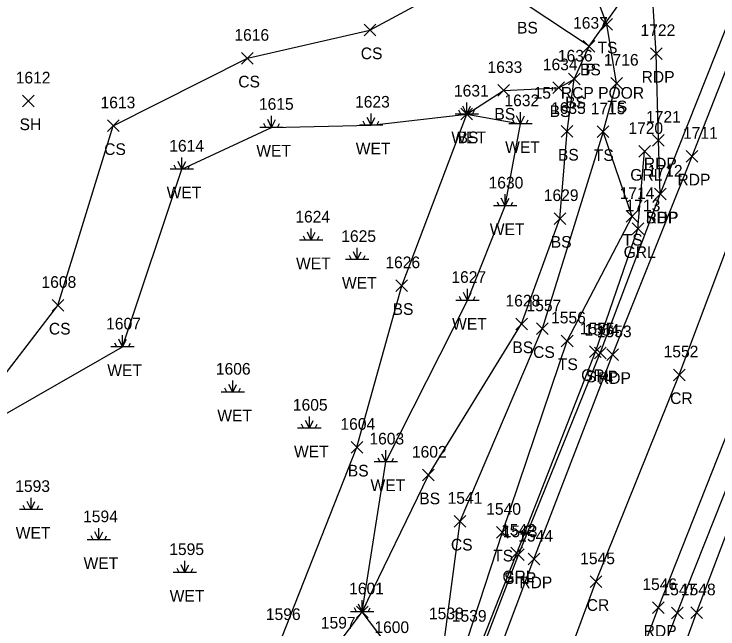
# Model space of a CAD drawing. Extents: x 1554917 to 1555870, y 813367 to 816333.
# Drawn here: x 1555138.3 to 1555258.8, y 814056.2 to 814161.6 of the extents above; entities that cross this region are included whole.
import ezdxf

# ---------------------------------------------------------------- set-up
doc = ezdxf.new("R2010")
doc.units = 0
for name, color, linetype in [('D_A', 7, 'Continuous'), ('D_C', 7, 'Continuous'), ('D_I', 7, 'Continuous'), ('D_TIC', 7, 'Continuous'), ('DCP', 7, 'Continuous'), ('L_A', 7, 'Continuous'), ('L_I', 7, 'Continuous'), ('L_TIC', 7, 'Continuous'), ('LELB', 7, 'Continuous'), ('LWET', 7, 'Continuous'), ('P_A', 7, 'Continuous'), ('P_I', 7, 'Continuous'), ('P_TIC', 7, 'Continuous'), ('PET', 7, 'Continuous'), ('PRC', 7, 'Continuous'), ('PSP', 7, 'Continuous'), ('R_A', 7, 'Continuous'), ('R_I', 7, 'Continuous'), ('R_TIC', 7, 'Continuous'), ('RGR', 7, 'Continuous')]:
    doc.layers.add(name, color=color, linetype=linetype)

msp = doc.modelspace()

# ---------------------------------------------------------------- linework, layer by layer
at = {"layer": 'D_TIC'}
for points in [[(1555235.77, 814155.09), (1555237.77, 814157.09)], [(1555237.77, 814155.09), (1555235.77, 814157.09)]]:
    msp.add_lwpolyline(points, dxfattribs=at)
at = {"layer": 'DCP'}
msp.add_lwpolyline([(1555236.77, 814156.09), (1555266.03, 814197.26)], dxfattribs=at)
at = {"layer": 'L_TIC'}
for points in [[(1555238.8, 814158.84), (1555240.8, 814160.84)], [(1555240.8, 814158.84), (1555238.8, 814160.84)], [(1555198.22, 814157.86), (1555200.22, 814159.86)], [(1555200.22, 814157.86), (1555198.22, 814159.86)], [(1555235.77, 814155.09), (1555237.77, 814157.09)], [(1555237.77, 814155.09), (1555235.77, 814157.09)], [(1555177.24, 814153.02), (1555179.24, 814155.02)], [(1555179.24, 814153.02), (1555177.24, 814155.02)], [(1555233.22, 814149.46), (1555235.22, 814151.46)], [(1555235.22, 814149.46), (1555233.22, 814151.46)], [(1555233.22, 814149.46), (1555235.22, 814151.46)], [(1555235.22, 814149.46), (1555233.22, 814151.46)], [(1555240.48, 814148.75), (1555242.48, 814150.75)], [(1555242.48, 814148.75), (1555240.48, 814150.75)], [(1555230.58, 814147.96), (1555232.58, 814149.96)], [(1555232.58, 814147.96), (1555230.58, 814149.96)], [(1555221.11, 814147.5), (1555223.11, 814149.5)], [(1555223.11, 814147.5), (1555221.11, 814149.5)], [(1555139.73, 814145.7), (1555141.73, 814147.7)], [(1555141.73, 814145.7), (1555139.73, 814147.7)], [(1555214.8, 814143.46), (1555216.8, 814145.46)], [(1555216.8, 814143.46), (1555214.8, 814145.46)], [(1555154.27, 814141.44), (1555156.27, 814143.44)], [(1555156.27, 814141.44), (1555154.27, 814143.44)], [(1555231.99, 814140.48), (1555233.99, 814142.48)], [(1555233.99, 814140.48), (1555231.99, 814142.48)], [(1555238.17, 814140.42), (1555240.17, 814142.42)], [(1555240.17, 814140.42), (1555238.17, 814142.42)], [(1555243.12, 814125.91), (1555245.12, 814127.91)], [(1555245.12, 814125.91), (1555243.12, 814127.91)], [(1555230.76, 814125.55), (1555232.76, 814127.55)], [(1555232.76, 814125.55), (1555230.76, 814127.55)], [(1555203.67, 814114.04), (1555205.67, 814116.04)], [(1555205.67, 814114.04), (1555203.67, 814116.04)], [(1555144.8, 814110.67), (1555146.8, 814112.67)], [(1555146.8, 814110.67), (1555144.8, 814112.67)], [(1555224.19, 814107.48), (1555226.19, 814109.48)], [(1555226.19, 814107.48), (1555224.19, 814109.48)], [(1555227.74, 814106.66), (1555229.74, 814108.66)], [(1555229.74, 814106.66), (1555227.74, 814108.66)], [(1555232.01, 814104.58), (1555234.01, 814106.58)], [(1555234.01, 814104.58), (1555232.01, 814106.58)], [(1555196, 814086.34), (1555198, 814088.34)], [(1555198, 814086.34), (1555196, 814088.34)], [(1555208.24, 814081.57), (1555210.24, 814083.57)], [(1555210.24, 814081.57), (1555208.24, 814083.57)], [(1555213.66, 814073.66), (1555215.66, 814075.66)], [(1555215.66, 814073.66), (1555213.66, 814075.66)], [(1555220.93, 814071.78), (1555222.93, 814073.78)], [(1555222.93, 814071.78), (1555220.93, 814073.78)], [(1555196.92, 814058.14), (1555198.92, 814060.14)], [(1555198.92, 814058.14), (1555196.92, 814060.14)], [(1555254.18, 814057.98), (1555256.18, 814059.98)], [(1555256.18, 814057.98), (1555254.18, 814059.98)]]:
    msp.add_lwpolyline(points, dxfattribs=at)
at = {"layer": 'LELB'}
for points in [[(1555161.57, 813925.65), (1555168.92, 813938.89), (1555173.57, 813945.95), (1555174.16, 813952.01), (1555182.4, 813974.26), (1555190.04, 813992.11), (1555201.74, 814019.14), (1555212.19, 814045.46), (1555215.96, 814054.45), (1555221.93, 814072.78), (1555233.01, 814105.58), (1555244.12, 814126.91), (1555239.17, 814141.42), (1555241.48, 814149.75), (1555239.8, 814159.84), (1555236.73, 814168.01), (1555231.65, 814185.57), (1555238.6, 814201.71), (1555239.91, 814224.12), (1555242.5, 814231.73), (1555248.59, 814255.34), (1555259.33, 814293.88), (1555265.42, 814329.58), (1555267.14, 814335.72)], [(1555103.83, 814081.29), (1555127.34, 814087.63), (1555145.8, 814111.67), (1555155.27, 814142.44), (1555178.24, 814154.02), (1555199.22, 814158.86), (1555221.17, 814170.73)], [(1555153.95, 813930.09), (1555158.29, 813940), (1555164.03, 813953.38), (1555164.41, 813963.6), (1555171.65, 813982.26), (1555182.05, 814007.23), (1555196.6, 814047.94), (1555202.45, 814046.5), (1555202.9, 814052.51), (1555197.92, 814059.14), (1555209.24, 814082.57), (1555225.19, 814108.48), (1555231.76, 814126.55), (1555232.99, 814141.48), (1555234.22, 814150.46), (1555236.77, 814156.09), (1555225.98, 814163.26)], [(1555146.26, 813968.15), (1555143.26, 813995.13), (1555159.28, 814011.16), (1555184.15, 814054.74), (1555197, 814087.34), (1555204.67, 814115.04), (1555215.8, 814144.46), (1555222.11, 814148.5), (1555231.58, 814148.96), (1555234.22, 814150.46)], [(1555239.17, 814141.42), (1555228.74, 814107.66)], [(1555244.11, 813903.09), (1555240.76, 813916.62), (1555228.48, 813937.37), (1555217.61, 813950.51), (1555215.58, 813954.88), (1555216.99, 813960.62), (1555222.34, 813976.41), (1555235.01, 814010.77), (1555239.56, 814017.88), (1555245.78, 814033.09), (1555255.18, 814058.98), (1555268.47, 814094.07), (1555274.97, 814112.22), (1555278.17, 814116.24), (1555282.02, 814117.52), (1555286.39, 814116.11), (1555289.99, 814109.88), (1555296.54, 814106.47), (1555313.61, 814126.36), (1555333.57, 814137.64)], [(1555212.19, 814045.46), (1555212.03, 814054.87), (1555214.66, 814074.66), (1555228.74, 814107.66)]]:
    msp.add_lwpolyline(points, dxfattribs=at)
at = {"layer": 'LWET'}
for p, q in [((1555215.8, 814144.46), (1555215.8, 814146.46)), ((1555214.8, 814144.46), (1555214.46, 814145.12)), ((1555215.8, 814144.46), (1555215.13, 814145.79)), ((1555215.8, 814144.46), (1555216.46, 814145.79)), ((1555216.8, 814144.46), (1555217.13, 814145.12)), ((1555225.01, 814142.8), (1555225.01, 814144.8)), ((1555225.01, 814142.8), (1555225.01, 814144.8)), ((1555182.39, 814142.18), (1555181.73, 814143.51)), ((1555182.39, 814142.18), (1555182.39, 814144.18)), ((1555182.39, 814142.18), (1555183.06, 814143.51)), ((1555199.42, 814142.56), (1555198.76, 814143.89)), ((1555199.42, 814142.56), (1555199.42, 814144.56)), ((1555199.42, 814142.56), (1555200.09, 814143.89)), ((1555217.8, 814144.46), (1555213.8, 814144.46)), ((1555225.01, 814142.8), (1555224.34, 814144.13)), ((1555225.01, 814142.8), (1555224.34, 814144.13)), ((1555225.01, 814142.8), (1555225.68, 814144.13)), ((1555225.01, 814142.8), (1555225.68, 814144.13)), ((1555181.39, 814142.18), (1555181.06, 814142.85)), ((1555183.39, 814142.18), (1555183.73, 814142.85)), ((1555201.42, 814142.56), (1555197.42, 814142.56)), ((1555198.42, 814142.56), (1555198.09, 814143.23)), ((1555200.42, 814142.56), (1555200.76, 814143.23)), ((1555227.01, 814142.8), (1555223.01, 814142.8)), ((1555227.01, 814142.8), (1555223.01, 814142.8)), ((1555224.01, 814142.8), (1555223.68, 814143.46)), ((1555224.01, 814142.8), (1555223.68, 814143.46)), ((1555226.01, 814142.8), (1555226.34, 814143.46)), ((1555226.01, 814142.8), (1555226.34, 814143.46)), ((1555184.39, 814142.18), (1555180.39, 814142.18)), ((1555167.03, 814135.02), (1555166.36, 814136.35)), ((1555167.03, 814135.02), (1555167.03, 814137.02)), ((1555167.03, 814135.02), (1555167.7, 814136.35)), ((1555166.03, 814135.02), (1555165.7, 814135.69)), ((1555168.03, 814135.02), (1555168.36, 814135.69)), ((1555169.03, 814135.02), (1555165.03, 814135.02)), ((1555222.38, 814128.7), (1555222.38, 814130.7)), ((1555221.38, 814128.7), (1555221.05, 814129.36)), ((1555222.38, 814128.7), (1555221.71, 814130.03)), ((1555222.38, 814128.7), (1555223.05, 814130.03)), ((1555223.38, 814128.7), (1555223.71, 814129.36)), ((1555224.38, 814128.7), (1555220.38, 814128.7)), ((1555189.19, 814122.87), (1555189.19, 814124.87)), ((1555188.19, 814122.87), (1555187.86, 814123.53)), ((1555189.19, 814122.87), (1555188.52, 814124.2)), ((1555189.19, 814122.87), (1555189.86, 814124.2)), ((1555190.19, 814122.87), (1555190.52, 814123.53)), ((1555191.19, 814122.87), (1555187.19, 814122.87)), ((1555197.06, 814119.54), (1555196.4, 814120.87)), ((1555197.06, 814119.54), (1555197.06, 814121.54)), ((1555197.06, 814119.54), (1555197.73, 814120.87)), ((1555199.06, 814119.54), (1555195.06, 814119.54)), ((1555196.06, 814119.54), (1555195.73, 814120.21)), ((1555198.06, 814119.54), (1555198.4, 814120.21)), ((1555215.92, 814112.52), (1555215.25, 814113.85)), ((1555215.92, 814112.52), (1555215.92, 814114.52)), ((1555215.92, 814112.52), (1555216.59, 814113.85)), ((1555217.92, 814112.52), (1555213.92, 814112.52)), ((1555214.92, 814112.52), (1555214.59, 814113.19)), ((1555216.92, 814112.52), (1555217.25, 814113.19)), ((1555156.87, 814104.54), (1555156.87, 814106.54)), ((1555155.87, 814104.54), (1555155.54, 814105.21)), ((1555156.87, 814104.54), (1555156.21, 814105.87)), ((1555156.87, 814104.54), (1555157.54, 814105.87)), ((1555157.87, 814104.54), (1555158.21, 814105.21)), ((1555158.87, 814104.54), (1555154.87, 814104.54)), ((1555175.72, 814096.79), (1555175.05, 814098.12)), ((1555175.72, 814096.79), (1555175.72, 814098.79)), ((1555175.72, 814096.79), (1555176.38, 814098.12)), ((1555177.72, 814096.79), (1555173.72, 814096.79)), ((1555174.72, 814096.79), (1555174.38, 814097.46)), ((1555176.72, 814096.79), (1555177.05, 814097.46)), ((1555188.85, 814090.62), (1555188.18, 814091.96)), ((1555188.85, 814090.62), (1555188.85, 814092.62)), ((1555188.85, 814090.62), (1555189.51, 814091.96)), ((1555190.85, 814090.62), (1555186.85, 814090.62)), ((1555187.85, 814090.62), (1555187.51, 814091.29)), ((1555189.85, 814090.62), (1555190.18, 814091.29)), ((1555201.96, 814084.83), (1555201.29, 814086.17)), ((1555201.96, 814084.83), (1555201.96, 814086.83)), ((1555201.96, 814084.83), (1555202.62, 814086.17)), ((1555203.96, 814084.83), (1555199.96, 814084.83)), ((1555200.96, 814084.83), (1555200.62, 814085.5)), ((1555202.96, 814084.83), (1555203.29, 814085.5)), ((1555141.18, 814076.69), (1555141.18, 814078.69)), ((1555140.18, 814076.69), (1555139.84, 814077.36)), ((1555141.18, 814076.69), (1555140.51, 814078.03)), ((1555141.18, 814076.69), (1555141.84, 814078.03)), ((1555142.18, 814076.69), (1555142.51, 814077.36)), ((1555143.18, 814076.69), (1555139.18, 814076.69)), ((1555152.8, 814071.5), (1555152.13, 814072.84)), ((1555152.8, 814071.5), (1555152.8, 814073.5)), ((1555152.8, 814071.5), (1555153.46, 814072.84)), ((1555154.8, 814071.5), (1555150.8, 814071.5)), ((1555151.8, 814071.5), (1555151.46, 814072.17)), ((1555153.8, 814071.5), (1555154.13, 814072.17)), ((1555167.55, 814065.88), (1555167.55, 814067.88)), ((1555166.55, 814065.88), (1555166.22, 814066.55)), ((1555167.55, 814065.88), (1555166.89, 814067.22)), ((1555167.55, 814065.88), (1555168.22, 814067.22)), ((1555168.55, 814065.88), (1555168.89, 814066.55)), ((1555169.55, 814065.88), (1555165.55, 814065.88)), ((1555197.92, 814059.14), (1555197.25, 814060.47)), ((1555197.92, 814059.14), (1555197.92, 814061.14)), ((1555197.92, 814059.14), (1555198.59, 814060.47)), ((1555199.92, 814059.14), (1555195.92, 814059.14)), ((1555196.92, 814059.14), (1555196.59, 814059.81)), ((1555198.92, 814059.14), (1555199.25, 814059.81))]:
    msp.add_line(p, q, dxfattribs=at)
for points in [[(1555103.17, 814066.14), (1555127.34, 814087.63), (1555156.87, 814104.54), (1555167.03, 814135.02), (1555182.39, 814142.18), (1555199.42, 814142.56), (1555215.8, 814144.46), (1555225.01, 814142.8)], [(1555079.52, 813972.15), (1555098.48, 813965.44), (1555111.92, 813965.76), (1555124.09, 813958.62), (1555134.73, 813947.78), (1555144.25, 813942.2), (1555154.27, 813942.5), (1555154.52, 813966.83), (1555160.01, 813989.73), (1555171.92, 814009.61), (1555193.51, 814053.28), (1555197.92, 814059.14), (1555201.96, 814084.83), (1555215.92, 814112.52), (1555222.38, 814128.7), (1555225.01, 814142.8)]]:
    msp.add_lwpolyline(points, dxfattribs=at)
at = {"layer": 'P_TIC'}
for points in [[(1555247.27, 814153.83), (1555249.27, 814155.83)], [(1555249.27, 814153.83), (1555247.27, 814155.83)], [(1555247.65, 814138.98), (1555249.65, 814140.98)], [(1555249.65, 814138.98), (1555247.65, 814140.98)], [(1555253.41, 814136.22), (1555255.41, 814138.22)], [(1555255.41, 814136.22), (1555253.41, 814138.22)], [(1555247.96, 814129.73), (1555249.96, 814131.73)], [(1555249.96, 814129.73), (1555247.96, 814131.73)], [(1555247.96, 814129.73), (1555249.96, 814131.73)], [(1555249.96, 814129.73), (1555247.96, 814131.73)], [(1555237.68, 814102.48), (1555239.68, 814104.48)], [(1555239.68, 814102.48), (1555237.68, 814104.48)], [(1555239.79, 814102.21), (1555241.79, 814104.21)], [(1555241.79, 814102.21), (1555239.79, 814104.21)], [(1555251.22, 814098.76), (1555253.22, 814100.76)], [(1555253.22, 814098.76), (1555251.22, 814100.76)], [(1555223.66, 814067.93), (1555225.66, 814069.93)], [(1555225.66, 814067.93), (1555223.66, 814069.93)], [(1555226.32, 814067.19), (1555228.32, 814069.19)], [(1555228.32, 814067.19), (1555226.32, 814069.19)], [(1555236.93, 814063.31), (1555238.93, 814065.31)], [(1555238.93, 814063.31), (1555236.93, 814065.31)], [(1555247.64, 814058.88), (1555249.64, 814060.88)], [(1555249.64, 814058.88), (1555247.64, 814060.88)], [(1555250.86, 814057.97), (1555252.86, 814059.97)], [(1555252.86, 814057.97), (1555250.86, 814059.97)]]:
    msp.add_lwpolyline(points, dxfattribs=at)
at = {"layer": 'PET'}
for points in [[(1555161.36, 813900.53), (1555183.5, 813956.99), (1555189.63, 813971.7), (1555196.36, 813987.75), (1555203.89, 814008), (1555206.01, 814012.95), (1555218.07, 814043.52), (1555227.32, 814068.19), (1555240.79, 814103.21), (1555254.41, 814137.22), (1555273.72, 814186.43), (1555286.72, 814219.57), (1555303.34, 814262.32), (1555319.11, 814302.56), (1555330.34, 814331.97)], [(1555182.57, 813892.25), (1555203.7, 813945.01), (1555216.85, 813978.34), (1555228.72, 814008.85), (1555239.47, 814035.47), (1555248.64, 814059.88), (1555262.92, 814096.01), (1555276.68, 814131.3), (1555286.36, 814156.33), (1555297.11, 814184.04), (1555306.67, 814209.51), (1555324.28, 814253.26), (1555340.35, 814293.54), (1555352.6, 814325.05)], [(1555248.96, 814130.73), (1555248.65, 814139.98), (1555248.27, 814154.83), (1555247.26, 814170.29), (1555253.74, 814178.64), (1555260.71, 814192.35), (1555263.33, 814182.56), (1555266.01, 814181.4), (1555270.99, 814187.05)]]:
    msp.add_lwpolyline(points, dxfattribs=at)
at = {"layer": 'PRC'}
msp.add_lwpolyline([(1554976.76, 813382.18), (1554992.84, 813427.9), (1555014.07, 813486.01), (1555030.62, 813532.31), (1555046.37, 813573.08), (1555064.69, 813621.19), (1555082.41, 813667.53), (1555112.1, 813744.1), (1555110.69, 813739.79), (1555136.16, 813805.74), (1555152.52, 813846.93), (1555172.03, 813896.18), (1555193.96, 813951.2), (1555206.37, 813983.4), (1555218.13, 814013.22), (1555228.65, 814039.26), (1555237.93, 814064.31), (1555252.22, 814099.76), (1555265.8, 814135.89), (1555275.26, 814160.09), (1555297.17, 814214.77), (1555313.83, 814257.94), (1555329.72, 814298.26), (1555342.03, 814329.92)], dxfattribs=at)
at = {"layer": 'PSP'}
for points in [[(1555160.79, 813906.47), (1555173.05, 813937.33), (1555179.42, 813953.63), (1555181.24, 813957.84), (1555186.72, 813973.16), (1555194.02, 813990.9), (1555204.38, 814016.29), (1555205.03, 814017.75), (1555215.29, 814044.5), (1555224.66, 814068.93), (1555238.68, 814103.48), (1555248.96, 814130.73), (1555261.62, 814162.67), (1555270.99, 814187.05), (1555283.98, 814220.8), (1555300.65, 814263.34), (1555316.51, 814303.51), (1555327.36, 814331.38)], [(1555197.67, 813922.42), (1555211.91, 813956.86), (1555220.23, 813977.15), (1555231.8, 814008.2), (1555242.48, 814034.48), (1555251.86, 814058.97), (1555266.04, 814094.8), (1555272.79, 814112.73), (1555286.23, 814147.2), (1555300.19, 814183.09), (1555310.34, 814208.22), (1555327.38, 814252.3), (1555343.49, 814292.44), (1555355.29, 814323.57)]]:
    msp.add_lwpolyline(points, dxfattribs=at)
at = {"layer": 'R_TIC'}
for points in [[(1555245.27, 814137.04), (1555247.27, 814139.04)], [(1555247.27, 814137.04), (1555245.27, 814139.04)], [(1555244.14, 814123.79), (1555246.14, 814125.79)], [(1555246.14, 814123.79), (1555244.14, 814125.79)], [(1555236.86, 814102.71), (1555238.86, 814104.71)], [(1555238.86, 814102.71), (1555236.86, 814104.71)], [(1555223.38, 814068.2), (1555225.38, 814070.2)], [(1555225.38, 814068.2), (1555223.38, 814070.2)]]:
    msp.add_lwpolyline(points, dxfattribs=at)
at = {"layer": 'RGR'}
msp.add_lwpolyline([(1555159.27, 813917.51), (1555164.57, 813923.33), (1555172.45, 813937.61), (1555174.85, 813944.62), (1555176.88, 813950.76), (1555185.36, 813973.38), (1555192.77, 813990.92), (1555204.01, 814018.12), (1555214.74, 814044.68), (1555224.38, 814069.2), (1555237.86, 814103.71), (1555245.14, 814124.79), (1555246.27, 814138.04)], dxfattribs=at)

# ---------------------------------------------------------------- texts
at = {"layer": 'D_A'}
msp.add_text('P', height=2, dxfattribs=at).set_placement((1555236.15, 814151.09))
at = {"layer": 'D_C'}
msp.add_text('15" RCP POOR', height=2, dxfattribs=at).set_placement((1555227.26, 814147.09))
at = {"layer": 'D_I'}
for s, p in [('1637', (1555234.03, 814159.09)), ('1596', (1555181.41, 814057.74))]:
    msp.add_text(s, height=2, dxfattribs=at).set_placement(p)
at = {"layer": 'L_A'}
for s, p in [('BS', (1555224.42, 814158.26)), ('TS', (1555238.21, 814154.84)), ('CS', (1555197.66, 814153.86)), ('BS', (1555235.21, 814151.09)), ('CS', (1555176.68, 814149.02)), ('BS', (1555232.66, 814145.46)), ('BS', (1555232.66, 814145.46)), ('BS', (1555230.02, 814143.96)), ('TS', (1555239.89, 814144.75)), ('BS', (1555220.55, 814143.5)), ('SH', (1555139.22, 814141.7)), ('WET', (1555213.17, 814139.46)), ('BS', (1555214.24, 814139.46)), ('CS', (1555153.71, 814137.44)), ('WET', (1555179.77, 814137.18)), ('WET', (1555196.8, 814137.56)), ('WET', (1555222.39, 814137.8)), ('WET', (1555222.39, 814137.8)), ('BS', (1555231.43, 814136.48)), ('TS', (1555237.58, 814136.42)), ('WET', (1555164.41, 814130.02)), ('WET', (1555219.76, 814123.7)), ('BS', (1555230.2, 814121.55)), ('TS', (1555242.53, 814121.91)), ('WET', (1555186.57, 814117.87)), ('WET', (1555194.44, 814114.54)), ('BS', (1555203.11, 814110.04)), ('CS', (1555144.24, 814106.67)), ('WET', (1555213.3, 814107.52)), ('BS', (1555223.63, 814103.48)), ('CS', (1555227.18, 814102.66)), ('TS', (1555231.42, 814100.58)), ('WET', (1555154.25, 814099.54)), ('WET', (1555173.09, 814091.79)), ('WET', (1555186.22, 814085.62)), ('BS', (1555195.44, 814082.34)), ('WET', (1555199.33, 814079.83)), ('BS', (1555207.68, 814077.57)), ('WET', (1555138.56, 814071.69)), ('CS', (1555213.1, 814069.66)), ('TS', (1555220.34, 814067.78)), ('WET', (1555150.18, 814066.5)), ('WET', (1555164.93, 814060.88))]:
    msp.add_text(s, height=2, dxfattribs=at).set_placement(p)
at = {"layer": 'L_I'}
for s, p in [('1637', (1555234.03, 814159.09)), ('1616', (1555176.01, 814157.02)), ('1636', (1555231.42, 814153.46)), ('1636', (1555231.42, 814153.46)), ('1716', (1555239.3, 814152.75)), ('1633', (1555219.37, 814151.5)), ('1634', (1555228.84, 814151.96)), ('1612', (1555138.56, 814149.7)), ('1631', (1555213.62, 814147.46)), ('1631', (1555213.62, 814147.46)), ('1613', (1555153.09, 814145.44)), ('1615', (1555180.22, 814145.18)), ('1623', (1555196.68, 814145.56)), ('1632', (1555222.27, 814145.8)), ('1632', (1555222.27, 814145.8)), ('1635', (1555230.25, 814144.48)), ('1715', (1555237.04, 814144.42)), ('1614', (1555164.86, 814138.02)), ('1630', (1555219.55, 814131.7)), ('1629', (1555229.01, 814129.55)), ('1714', (1555242, 814129.91)), ('1624', (1555186.45, 814125.87)), ('1625', (1555194.32, 814122.54)), ('1626', (1555201.87, 814118.04)), ('1627', (1555213.18, 814115.52)), ('1608', (1555142.98, 814114.67)), ('1628', (1555222.45, 814111.48)), ('1557', (1555226.05, 814110.66)), ('1556', (1555230.26, 814108.58)), ('1607', (1555154.05, 814107.54)), ('1606', (1555172.84, 814099.79)), ('1605', (1555186.03, 814093.62)), ('1604', (1555194.18, 814090.34)), ('1603', (1555199.14, 814087.83)), ('1602', (1555206.42, 814085.57)), ('1593', (1555138.48, 814079.69)), ('1541', (1555212.53, 814077.66)), ('1540', (1555219.15, 814075.78)), ('1594', (1555150.1, 814074.5)), ('1595', (1555164.86, 814068.88)), ('1601', (1555195.67, 814062.14)), ('1601', (1555195.67, 814062.14)), ('1548', (1555252.49, 814061.98)), ('1596', (1555181.41, 814057.74)), ('1538', (1555209.34, 814057.87)), ('1539', (1555213.26, 814057.45)), ('1597', (1555190.82, 814056.28)), ('1600', (1555199.99, 814055.51))]:
    msp.add_text(s, height=2, dxfattribs=at).set_placement(p)
at = {"layer": 'P_A'}
for s, p in [('RDP', (1555245.76, 814149.83)), ('RDP', (1555246.14, 814134.98)), ('RDP', (1555251.9, 814132.22)), ('SHP', (1555246.49, 814125.73)), ('RDP', (1555246.44, 814125.73)), ('SHP', (1555236.22, 814098.48)), ('RDP', (1555238.28, 814098.21)), ('CR', (1555250.65, 814094.76)), ('SHP', (1555222.2, 814063.93)), ('RDP', (1555224.81, 814063.19)), ('CR', (1555236.36, 814059.31)), ('RDP', (1555246.12, 814054.88))]:
    msp.add_text(s, height=2, dxfattribs=at).set_placement(p)
at = {"layer": 'P_I'}
for s, p in [('1722', (1555245.58, 814157.83)), ('1721', (1555246.53, 814142.98)), ('1711', (1555252.85, 814140.22)), ('1712', (1555246.83, 814133.73)), ('1712', (1555246.83, 814133.73)), ('1554', (1555235.99, 814106.48)), ('1553', (1555238.1, 814106.21)), ('1552', (1555249.53, 814102.76)), ('1543', (1555221.97, 814071.93)), ('1544', (1555224.63, 814071.19)), ('1545', (1555235.24, 814067.31)), ('1546', (1555245.89, 814062.88)), ('1547', (1555249.17, 814061.97))]:
    msp.add_text(s, height=2, dxfattribs=at).set_placement(p)
at = {"layer": 'R_A'}
for p in [(1555243.82, 814133.04), (1555242.68, 814119.79), (1555235.41, 814098.71), (1555221.92, 814064.2)]:
    msp.add_text('GRL', height=2, dxfattribs=at).set_placement(p)
at = {"layer": 'R_I'}
for s, p in [('1720', (1555243.49, 814141.04)), ('1713', (1555243.02, 814127.79)), ('1555', (1555235.17, 814106.71)), ('1542', (1555221.69, 814072.2))]:
    msp.add_text(s, height=2, dxfattribs=at).set_placement(p)

doc.saveas('drawing.dxf')
